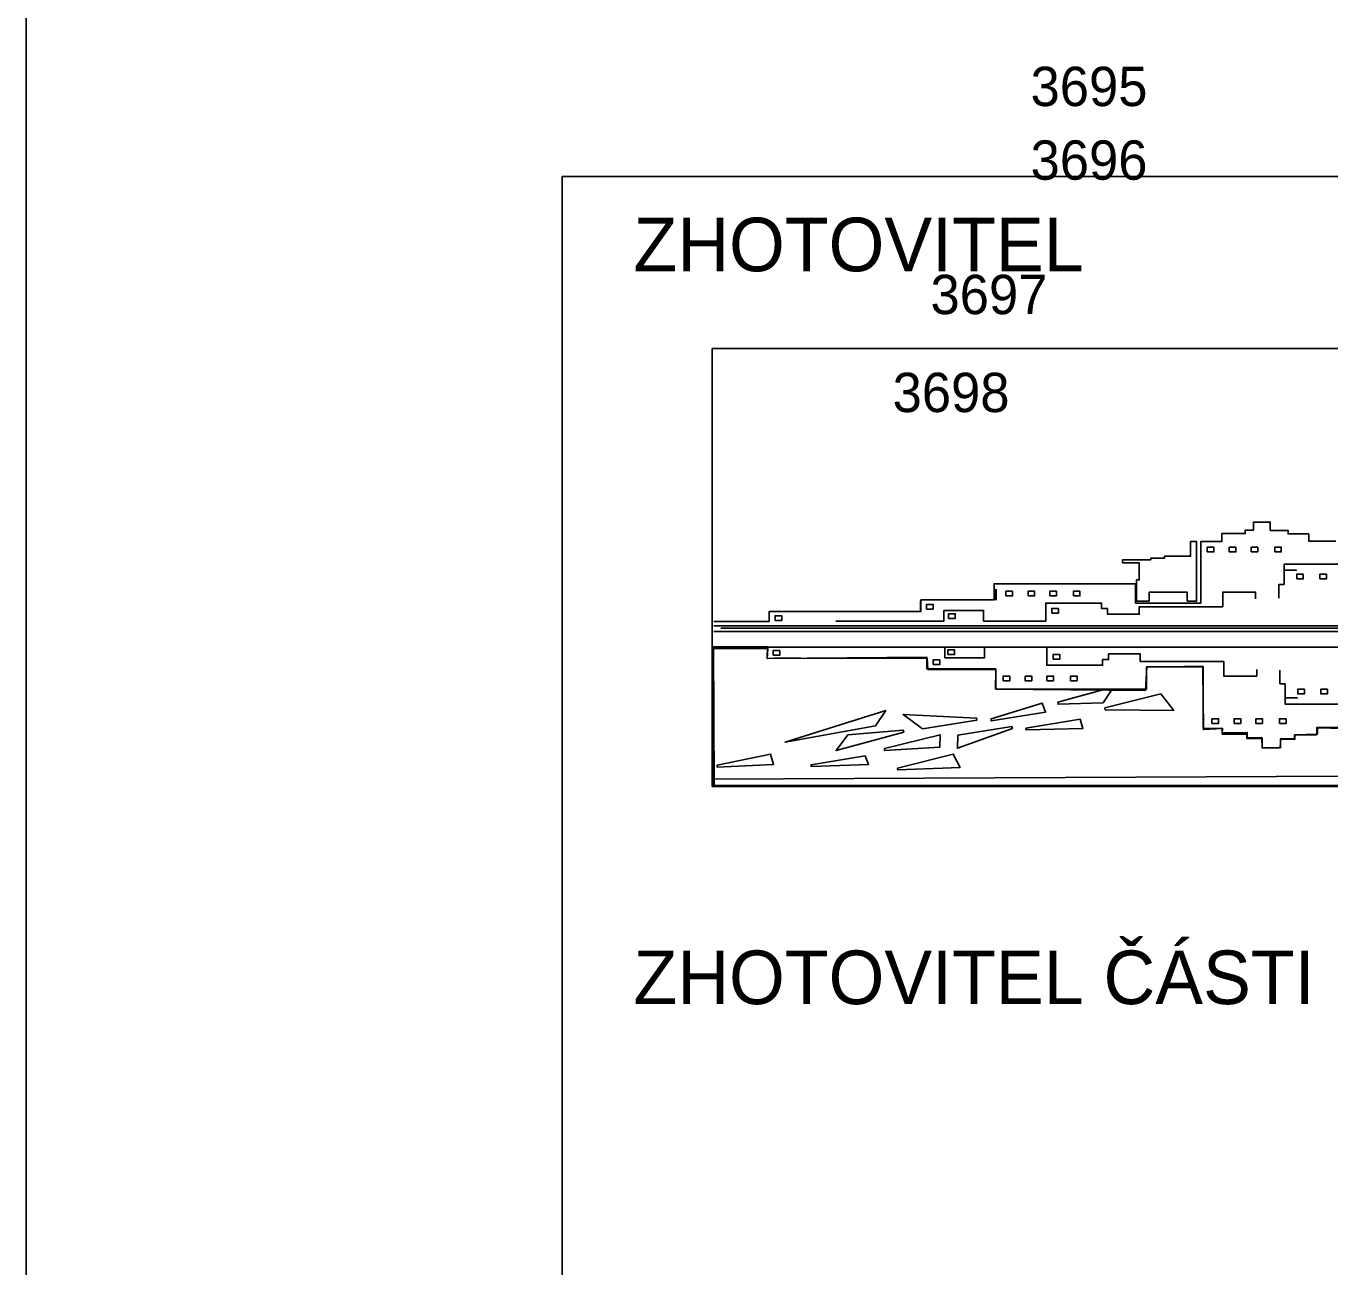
# Model space of a CAD drawing. Extents: x -740053 to -737517, y -1033516 to -1032476.
# Drawn here: x -738969.08 to -738950.84, y -1032585.46 to -1032568.1 of the extents above; entities that cross this region are included whole.
import ezdxf

# ---------------------------------------------------------------- set-up
doc = ezdxf.new("R2010")
doc.units = 0
for name, color, linetype in [('bod-cislo', 7, 'Continuous'), ('promika-formát', 7, 'Continuous'), ('promika-rozp', 7, 'Continuous')]:
    doc.layers.add(name, color=color, linetype=linetype)

# ---------------------------------------------------------------- blocks, each defined once
blk = doc.blocks.new('onegast')
for p, q in [((9.252, 6.105), (9.252, 6.463)), ((9.309, 6.102), (9.309, 6.46)), ((6.825, 5.723), (6.825, 6.082)), ((0.046, 5.264), (49.513, 5.263)), ((0.278, 5.186), (49.435, 5.186)), ((0.046, 5.075), (49.427, 5.075)), ((0.046, 4.561), (49.435, 4.561))]:
    blk.add_line(p, q)
for points in [[(0, 14.352), (49.53, 14.352), (49.53, 0), (0, 0)], [(19.161, 6.799), (19.377, 6.799), (19.377, 6.95), (19.161, 6.95)], [(12.874, 2.574), (14.701, 3.028), (15.132, 2.483), (12.879, 2.512)], [(19.195, 3.182), (19.411, 3.182), (19.411, 3.031), (19.195, 3.031)], [(9.139, 2.21), (10.813, 2.729), (10.929, 2.436), (9.143, 2.148)], [(3.464, 1.792), (5.689, 2.483), (5.353, 1.985), (2.388, 1.451)], [(6.257, 2.359), (8.663, 2.239), (8.678, 2.175), (6.892, 1.886)], [(10.285, 1.911), (12.061, 2.202), (12.15, 1.899), (10.289, 1.849)], [(4.449, 1.687), (6.263, 1.842), (6.277, 1.778), (4.06, 1.174)], [(8.049, 1.674), (9.825, 1.965), (9.84, 1.9), (8.039, 1.247)], [(5.644, 1.239), (7.471, 1.693), (7.457, 1.283), (5.649, 1.176)], [(0.161, 0.692), (1.912, 1.059), (2.012, 0.718), (0.165, 0.63)], [(3.24, 0.71), (5.016, 1), (5.119, 0.715), (3.244, 0.648)], [(6.077, 0.602), (7.903, 1.057), (8.126, 0.622), (6.081, 0.54)]]:
    blk.add_lwpolyline(points, close=True)
for points in [[(0.046, 5.405), (1.862, 5.405), (1.862, 5.731), (6.84, 5.731), (6.84, 6.109), (9.238, 6.109), (9.238, 6.643), (13.878, 6.643), (13.878, 6.005), (16.015, 6.005), (16.015, 8.023), (16.706, 8.023), (16.706, 8.284), (17.475, 8.284), (17.475, 8.401), (17.749, 8.401), (17.749, 8.662), (18.296, 8.662), (18.296, 8.388), (18.879, 8.388), (18.879, 8.272), (19.556, 8.272), (19.556, 8.037), (20.443, 8.037)], [(14.328, 6.074), (13.905, 6.074), (13.905, 6.765), (14, 6.765), (14, 7.326), (13.453, 7.326), (13.453, 7.425), (14.378, 7.425), (14.378, 7.475), (14.825, 7.475), (14.825, 7.544), (15.233, 7.544), (15.273, 7.544), (15.68, 7.544), (15.68, 8.021), (15.879, 8.021), (15.879, 6.074), (15.571, 6.074), (15.571, 6.362), (14.328, 6.362), (14.328, 6.074)], [(16.228, 7.685), (16.444, 7.685), (16.444, 7.836), (16.228, 7.836), (16.228, 7.685)], [(16.952, 7.685), (17.168, 7.685), (17.168, 7.836), (16.952, 7.836), (16.952, 7.685)], [(17.666, 7.685), (17.882, 7.685), (17.882, 7.836), (17.666, 7.836), (17.666, 7.685)], [(18.439, 7.685), (18.655, 7.685), (18.655, 7.836), (18.439, 7.836), (18.439, 7.685)], [(18.576, 6.169), (18.576, 6.617), (18.746, 6.617), (18.746, 7.081), (19.149, 7.081), (19.149, 7.081), (18.746, 7.081), (18.746, 7.282), (22.862, 7.282), (22.862, 7.282), (22.862, 7.183), (22.396, 7.183), (22.396, 7.088), (22.871, 7.088), (22.871, 6.157)], [(19.919, 6.799), (20.135, 6.799), (20.135, 6.95), (19.919, 6.95), (19.919, 6.799)], [(4.051, 5.42), (7.596, 5.42), (7.596, 5.765), (8.897, 5.765), (8.897, 5.42), (10.933, 5.42), (10.933, 6.01), (12.761, 6.01), (12.761, 5.826), (12.957, 5.826), (12.957, 5.643), (14, 5.643), (14, 5.888), (16.736, 5.888), (16.736, 6.366), (17.815, 6.366), (17.815, 6.145)], [(9.628, 6.243), (9.844, 6.243), (9.844, 6.394), (9.628, 6.394), (9.628, 6.243)], [(10.353, 6.243), (10.569, 6.243), (10.569, 6.394), (10.353, 6.394), (10.353, 6.243)], [(11.067, 6.243), (11.283, 6.243), (11.283, 6.394), (11.067, 6.394), (11.067, 6.243)], [(11.839, 6.243), (12.055, 6.243), (12.055, 6.394), (11.839, 6.394), (11.839, 6.243)], [(2.06, 5.439), (2.276, 5.439), (2.276, 5.591), (2.06, 5.591), (2.06, 5.439)], [(7.024, 5.813), (7.24, 5.813), (7.24, 5.964), (7.024, 5.964), (7.024, 5.813)], [(7.749, 5.505), (7.965, 5.505), (7.965, 5.656), (7.749, 5.656), (7.749, 5.505)], [(11.131, 5.681), (11.348, 5.681), (11.348, 5.832), (11.131, 5.832), (11.131, 5.681)], [(0.02, 0.014), (23.093, 0.002)], [(20.708, 1.897), (19.841, 1.924), (19.841, 1.714), (19.819, 1.714), (19.819, 1.69), (19.163, 1.69), (19.103, 1.687), (19.103, 1.544), (18.635, 1.544), (18.625, 1.386), (18.625, 1.266), (18.256, 1.266), (18.026, 1.258), (18.017, 1.57), (17.525, 1.57), (17.525, 1.716), (16.716, 1.716), (16.716, 1.896), (16.101, 1.86), (16.101, 1.902), (16.093, 1.902), (16.093, 2.719), (16.083, 3.915), (14.514, 3.915), (14.249, 3.911), (14.237, 3.714), (14.237, 3.187), (14.206, 3.187), (14.203, 3.146), (13.089, 3.156), (12.812, 2.735), (11.338, 2.693), (11.334, 2.755), (12.803, 3.159), (9.776, 3.187), (9.292, 3.187), (9.292, 3.191), (9.287, 3.191), (9.292, 3.593), (9.292, 3.82), (7.066, 3.831), (7.065, 3.849), (7.039, 3.849), (7.039, 4.196), (2.893, 4.204), (2.028, 4.198), (1.802, 4.187), (1.803, 4.196), (1.802, 4.196), (1.81, 4.518), (0.042, 4.506), (0.02, 0.014)], [(0.042, 4.506), (0.03, 0.238), (23.125, 0.347)], [(20.708, 1.897), (19.841, 1.924), (19.841, 1.714), (19.093, 1.687), (19.093, 1.559), (18.637, 1.568), (18.619, 1.277), (18.026, 1.258), (18.017, 1.605), (17.542, 1.596), (17.542, 1.769), (16.721, 1.751), (16.73, 1.897), (16.101, 1.86), (16.083, 3.939), (14.249, 3.911), (14.203, 3.146), (9.287, 3.191), (9.296, 3.82), (7.066, 3.831), (7.048, 4.196), (2.185, 4.205), (1.802, 4.187), (1.821, 4.518), (0.042, 4.506)], [(0.036, 4.579), (0.065, 0.028), (23.119, 0.038)], [(20.694, 1.928), (19.819, 1.928), (19.819, 1.69), (19.103, 1.69), (19.103, 1.544), (18.625, 1.544), (18.625, 1.266), (18.029, 1.266), (18.029, 1.57), (17.525, 1.57), (17.525, 1.716), (16.716, 1.716), (16.716, 1.902), (16.093, 1.902), (16.093, 3.915), (14.237, 3.915), (14.237, 3.187), (9.292, 3.187), (9.292, 3.849), (7.039, 3.849), (7.039, 4.233), (1.802, 4.196), (1.811, 4.57), (0.036, 4.579)], [(1.994, 4.298), (2.21, 4.298), (2.21, 4.449), (1.994, 4.449), (1.994, 4.298)], [(4.084, 4.561), (7.63, 4.561), (7.63, 4.216), (8.93, 4.216), (8.93, 4.561), (10.967, 4.561), (10.967, 3.971), (12.794, 3.971), (12.794, 4.155), (12.991, 4.155), (12.991, 4.339), (14.034, 4.339), (14.034, 4.094), (16.769, 4.094), (16.769, 3.616), (17.849, 3.616), (17.849, 3.836)], [(7.727, 4.32), (7.943, 4.32), (7.943, 4.471), (7.727, 4.471), (7.727, 4.32)], [(11.175, 4.166), (11.391, 4.166), (11.391, 4.317), (11.175, 4.317), (11.175, 4.166)], [(7.243, 3.99), (7.46, 3.99), (7.46, 4.142), (7.243, 4.142), (7.243, 3.99)], [(9.536, 3.464), (9.752, 3.464), (9.752, 3.615), (9.536, 3.615), (9.536, 3.464)], [(10.26, 3.464), (10.476, 3.464), (10.476, 3.615), (10.26, 3.615), (10.26, 3.464)], [(10.974, 3.464), (11.19, 3.464), (11.19, 3.615), (10.974, 3.615), (10.974, 3.464)], [(11.746, 3.464), (11.963, 3.464), (11.963, 3.615), (11.746, 3.615), (11.746, 3.464)], [(18.61, 3.813), (18.61, 3.364), (18.78, 3.364), (18.78, 2.9), (19.182, 2.9), (19.182, 2.9), (18.78, 2.9), (18.78, 2.699), (22.895, 2.699), (22.895, 2.699), (22.895, 2.799), (22.429, 2.799), (22.429, 2.894), (22.904, 2.894), (22.904, 3.824)], [(15.132, 2.483), (12.879, 2.512), (12.874, 2.574), (14.701, 3.028), (15.132, 2.483)], [(19.195, 3.031), (19.195, 3.182), (19.411, 3.182), (19.411, 3.031), (19.195, 3.031)], [(20.169, 3.031), (19.953, 3.031), (19.953, 3.182), (20.169, 3.182), (20.169, 3.031)], [(9.143, 2.148), (9.139, 2.21), (10.813, 2.729), (10.929, 2.436), (9.143, 2.148)], [(2.388, 1.451), (3.464, 1.792), (5.689, 2.483), (5.353, 1.985), (2.388, 1.451)], [(6.892, 1.886), (6.257, 2.359), (8.663, 2.239), (8.678, 2.175), (6.892, 1.886)], [(10.289, 1.849), (10.285, 1.911), (12.061, 2.202), (12.15, 1.899), (10.289, 1.849)], [(16.383, 2.065), (16.599, 2.065), (16.599, 2.216), (16.383, 2.216), (16.383, 2.065)], [(17.107, 2.065), (17.324, 2.065), (17.324, 2.216), (17.107, 2.216), (17.107, 2.065)], [(17.821, 2.065), (18.037, 2.065), (18.037, 2.216), (17.821, 2.216), (17.821, 2.065)], [(18.594, 2.065), (18.81, 2.065), (18.81, 2.216), (18.594, 2.216), (18.594, 2.065)], [(4.06, 1.174), (4.449, 1.687), (6.263, 1.842), (6.277, 1.778), (4.06, 1.174)], [(8.039, 1.247), (8.049, 1.674), (9.825, 1.965), (9.84, 1.9), (8.039, 1.247)], [(5.649, 1.176), (5.644, 1.239), (7.471, 1.693), (7.457, 1.283), (5.649, 1.176)], [(0.165, 0.63), (0.161, 0.692), (1.912, 1.059), (2.012, 0.718), (0.165, 0.63)], [(3.244, 0.648), (3.24, 0.71), (5.016, 1), (5.119, 0.715), (3.244, 0.648)], [(6.081, 0.54), (6.077, 0.602), (7.903, 1.057), (8.126, 0.622), (6.081, 0.54)]]:
    blk.add_lwpolyline(points)

msp = doc.modelspace()

# ---------------------------------------------------------------- linework, layer by layer
at = {"layer": 'promika-formát'}
msp.add_lwpolyline([(-738969.082, -1032624.959), (-738864.082, -1032624.959), (-738864.082, -1032476.459), (-738969.082, -1032476.459)], close=True, dxfattribs=at)
at = {"layer": 'promika-rozp'}
msp.add_lwpolyline([(-738961.582, -1032590.709), (-738961.582, -1032570.209), (-738871.582, -1032570.209), (-738871.582, -1032590.709)], dxfattribs=at)

# ---------------------------------------------------------------- block references
at = {"xscale": 0.4267458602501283, "yscale": 0.4267458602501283}
msp.add_blockref('onegast', (-738959.481, -1032578.738), dxfattribs=at)

# ---------------------------------------------------------------- texts
at = {"layer": 'bod-cislo'}
for s, p in [('3695', (-738955.028, -1032569.223)), ('3696', (-738955.028, -1032570.253)), ('3697', (-738956.428, -1032572.133)), ('3698', (-738956.958, -1032573.503))]:
    msp.add_text(s, height=0.55, dxfattribs=at).set_placement(p)
at = {"layer": 'promika-rozp'}
for s, p in [('ZHOTOVITEL', (-738960.583, -1032571.534)), ('ZHOTOVITEL ČÁSTI', (-738960.583, -1032581.784))]:
    msp.add_text(s, height=0.75, dxfattribs=at).set_placement(p)

doc.saveas('drawing.dxf')
